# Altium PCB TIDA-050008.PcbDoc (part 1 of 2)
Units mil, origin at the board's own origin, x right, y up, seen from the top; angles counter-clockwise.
Board outline 3500 x 2500 mil, 4 copper layers (Top Layer, Signal Layer 1, Signal Layer 2, Bottom Layer), stack 38.4 mil thick; 136 components, 48 nets, 303 pads, 230 vias.
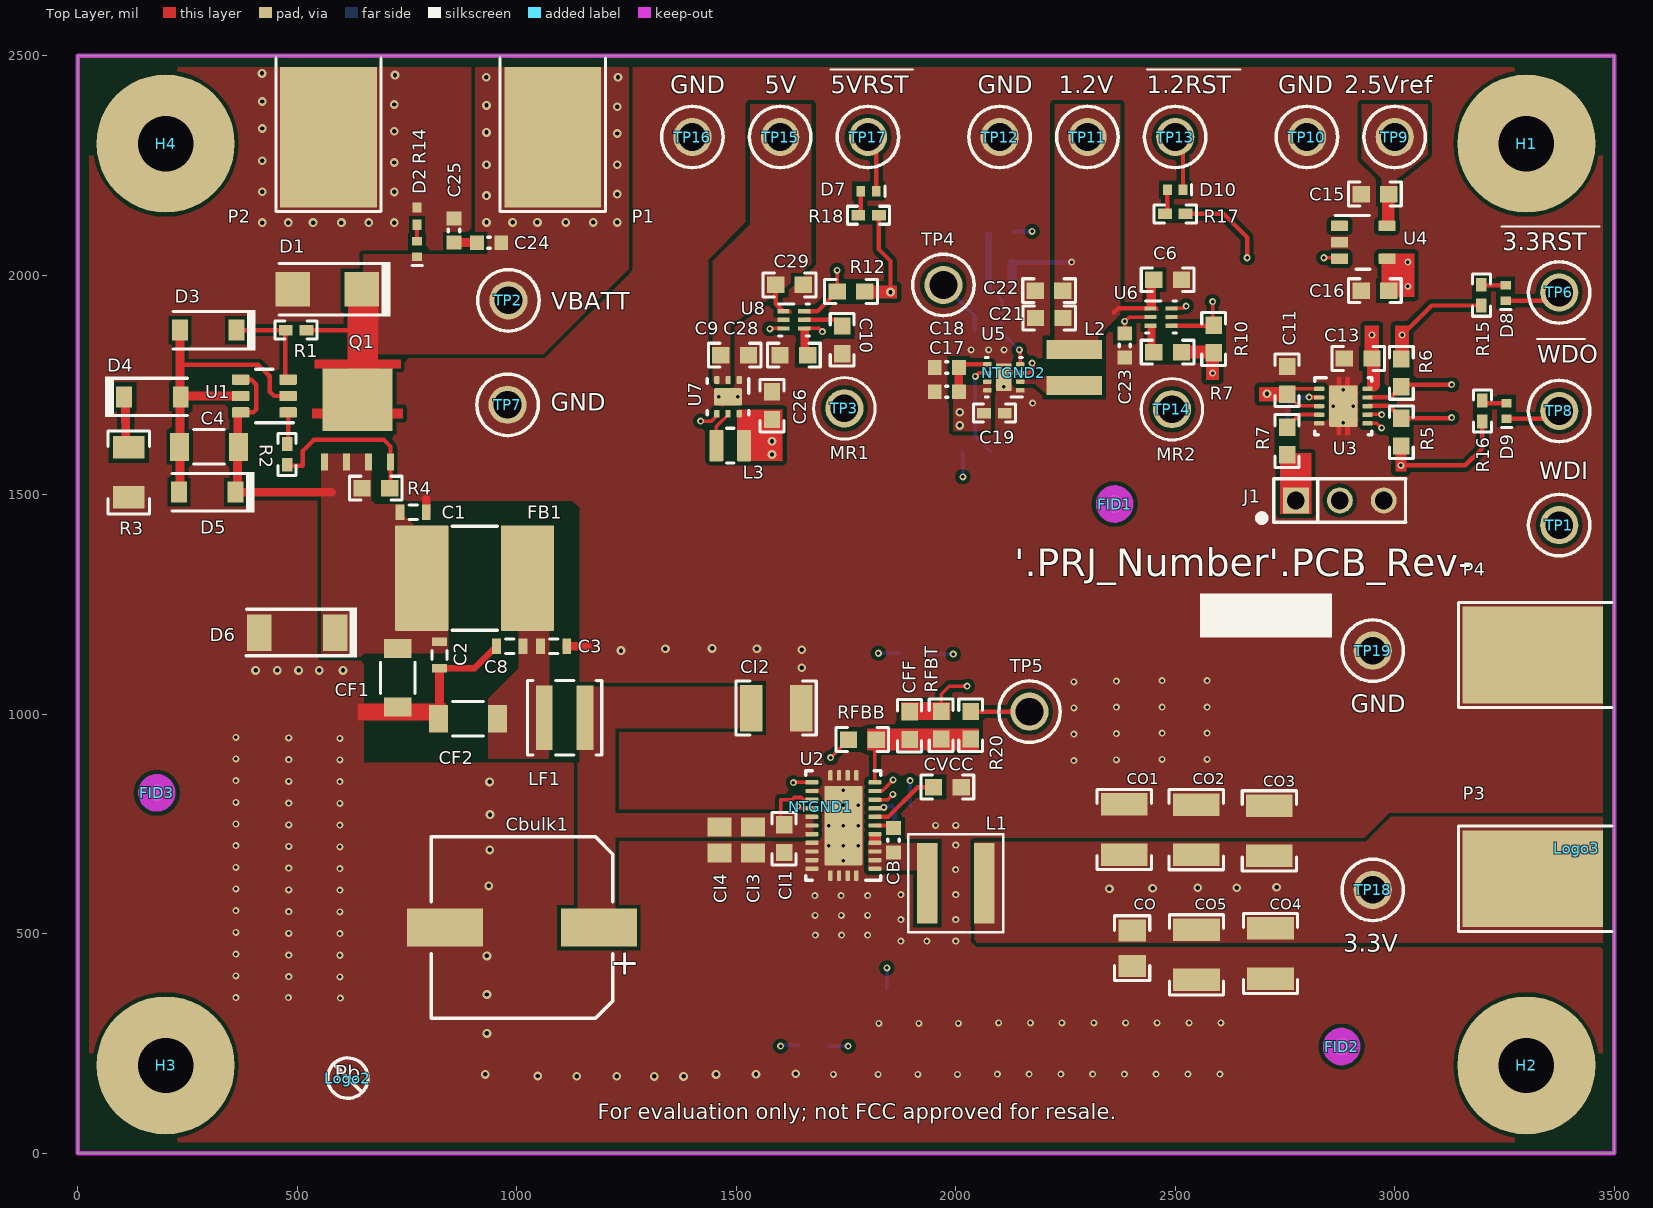
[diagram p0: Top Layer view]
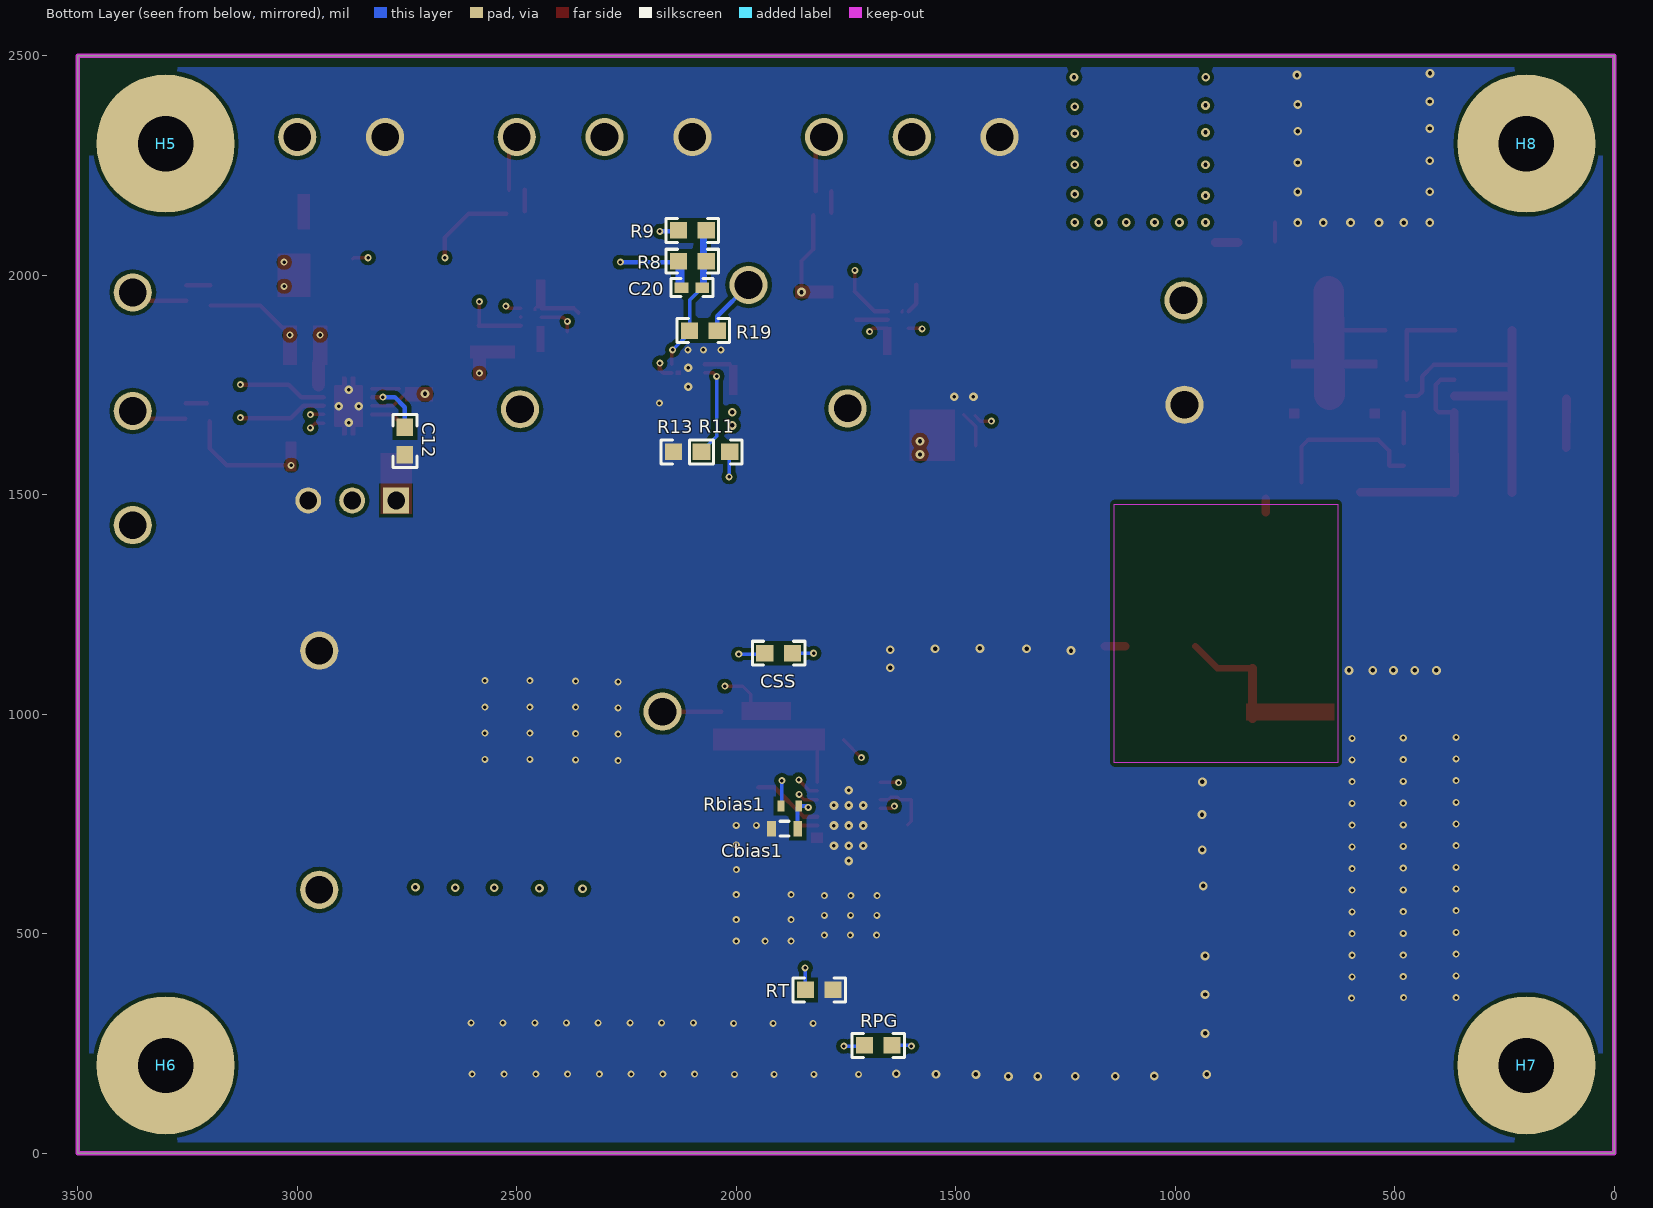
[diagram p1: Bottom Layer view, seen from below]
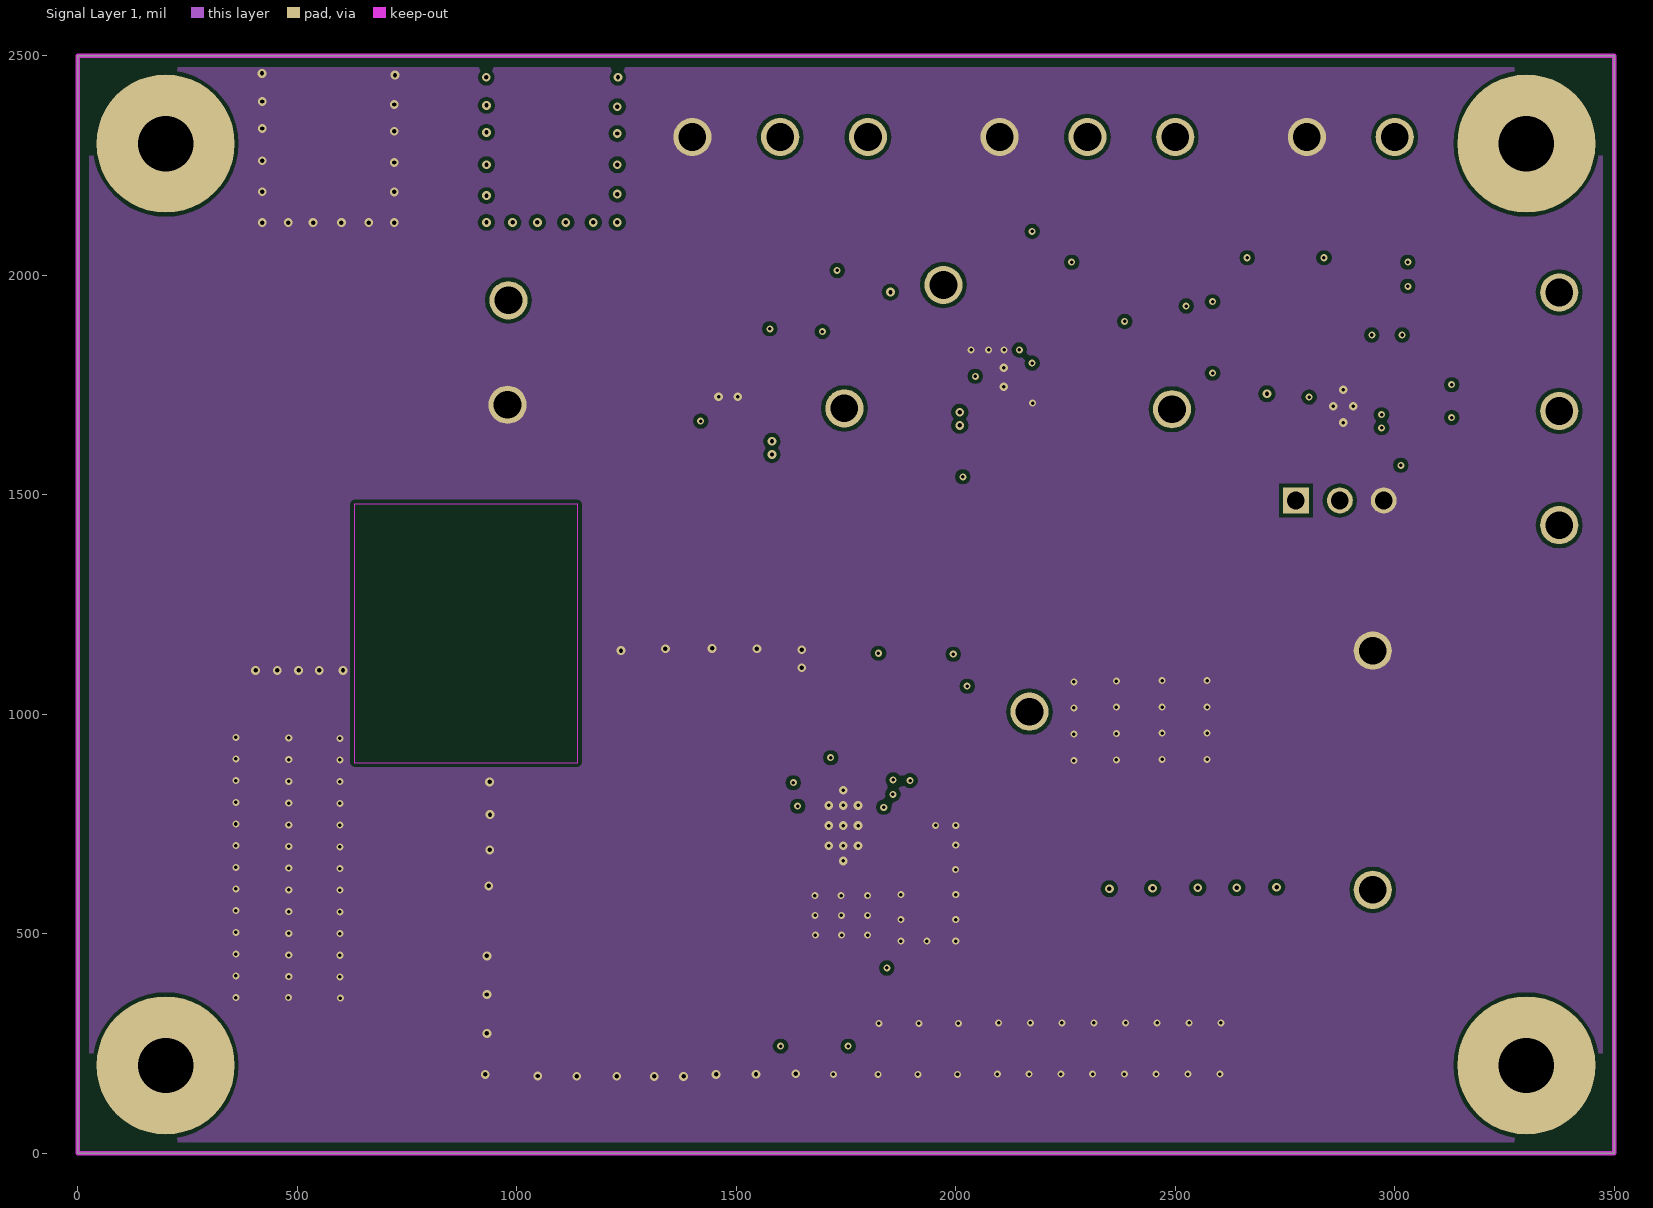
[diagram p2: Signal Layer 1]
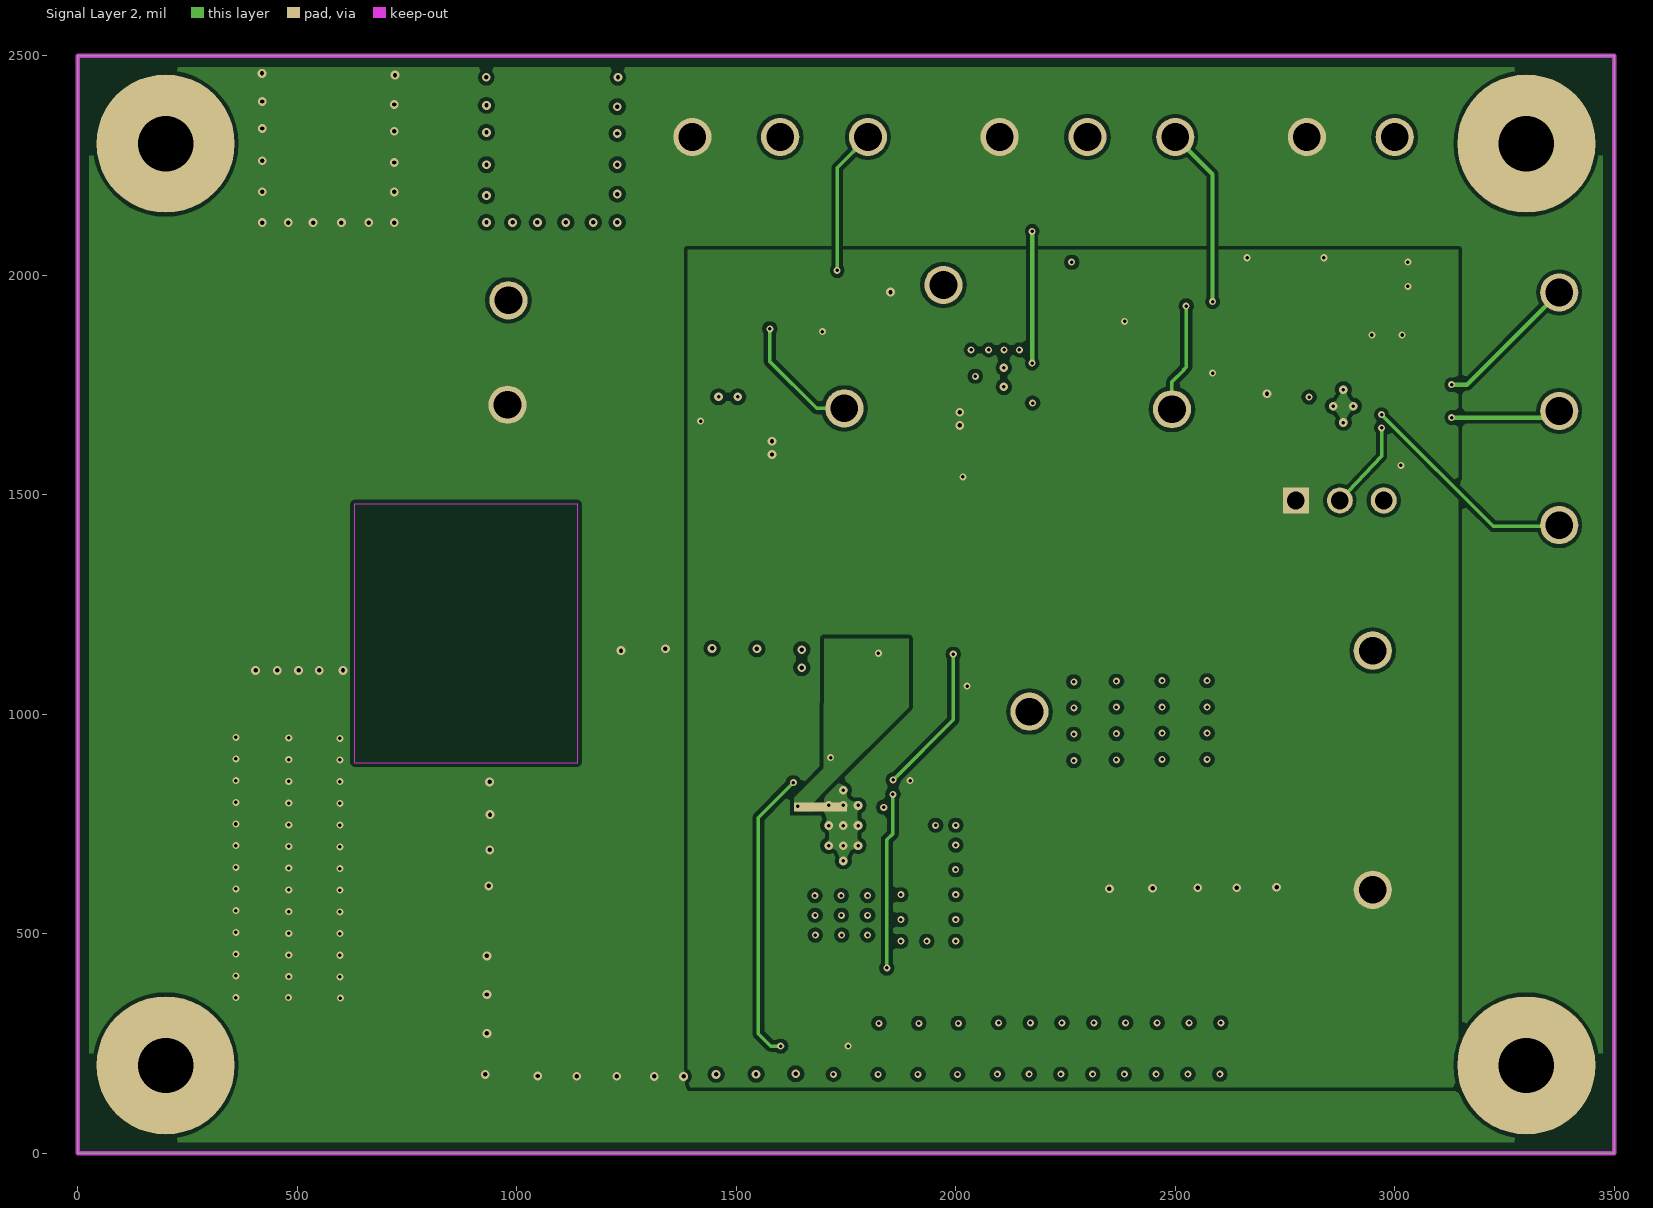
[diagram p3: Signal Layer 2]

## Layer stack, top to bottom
Top Solder: solder mask 0.4, Solder Resist, Dk 3.5
Top Layer: signal copper 2.8
Dielectric1: core 10, FR-4, Dk 4.2
Signal Layer 1: signal copper 1.4
Dielectric 2: core 10, FR-4, Dk 4.2
Signal Layer 2: signal copper 1.4
Dielectric3: core 10, FR-4, Dk 4.2
Bottom Layer: signal copper 2.8
Bottom Solder: solder mask 0.4, Solder Resist, Dk 3.5

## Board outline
0,0 3500,0 3500,2500 0,2500

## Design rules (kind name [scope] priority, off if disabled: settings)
AcuteAngle [All] p1: minimum=4.50000000000000E+0001 checktracksonly=FALSE
AssemblyTestPointUsage [All] p1: valid=2
BoardOutlineClearance BoardOutlineClearance_MountingHoles [OnCopper and InComponentClass('Mounting Holes')] p1: gap=40 ignorepadtopadclearanceinfootprint=FALSE
BoardOutlineClearance BoardOutlineClearance_Poly [OnCopper and IsPoly] p2: gap=25 ignorepadtopadclearanceinfootprint=FALSE
BoardOutlineClearance [OnCopper and Not InComponentClass('Logo') and not InComponentClass('FiducialMark') and not InRegion(1000,500,4000,800) and not InPoly] p3: gap=25 ignorepadtopadclearanceinfootprint=FALSE
Clearance Clearance_1 [(InNet('1.2RESET') AND InComponent('C1'))] p1: gap=10 ignorepadtopadclearanceinfootprint=FALSE except(0: Arc-Hole Track-Hole SMDPad-Hole THPad-Hole Via-Hole Fill-Hole Poly-Hole Region-Hole Text-Hole)
Clearance Clearance_Keepouts [((IsTrack Or IsArc) And Not InPoly) And IsFree and IsKeepOut vs ((IsTrack Or IsArc) And Not InPoly) And IsFree and IsKeepOut] p2: gap=0 ignorepadtopadclearanceinfootprint=FALSE
Clearance Clearance_Poly [InPolygon] p3: gap=9 ignorepadtopadclearanceinfootprint=FALSE except(0: Arc-Hole Track-Hole SMDPad-Hole THPad-Hole Via-Hole Fill-Hole Poly-Hole Region-Hole Text-Hole)
Clearance Clearance_FiducialMark [IsKeepOut and InComponentClass('FiducialMark') vs IsPad and InComponentClass('FiducialMark')] p4: gap=0 ignorepadtopadclearanceinfootprint=FALSE
Clearance [All] p5: gap=4 ignorepadtopadclearanceinfootprint=FALSE
ComponentClearance ComponentClearance_R11andR13 [InComponent('R11') vs InComponent('R13')] p1: gap=-1 collisioncheckmode=3 verticalgap=10 showdistances=FALSE
ComponentClearance ComponentClearance_NetTietoGND [(InComponent('NTGND1') OR InComponent('NTGND2')) vs (InComponent('U2') OR InComponent('U5'))] p2: gap=-1 collisioncheckmode=3 verticalgap=10 showdistances=FALSE
ComponentClearance ComponentClearance_MountingHoles_FiducialMarks [InComponentClass('Mounting Holes') vs InComponentClass('FiducialMark')] p3: gap=50 collisioncheckmode=3 verticalgap=10 showdistances=FALSE
ComponentClearance ComponentClearance_Shunt [InComponentClass('Header') vs InComponentClass('Shunt')] p4: gap=0 collisioncheckmode=3 verticalgap=0 showdistances=FALSE
ComponentClearance ComponentClearance_Logo [InComponentClass('Logo')] p5: gap=50 collisioncheckmode=3 verticalgap=10 showdistances=FALSE
ComponentClearance ComponentClearance_ScrewToNut [(HasFootprint('NY PMS 440 0025 PH')) vs (HasFootprint('Keystone_1902C'))] p6: gap=5 collisioncheckmode=3 verticalgap=10 showdistances=FALSE
ComponentClearance ComponentClearance_MountingHoles [InComponentClass('Mounting Holes')] p7: gap=100 collisioncheckmode=3 verticalgap=100000 showdistances=FALSE
ComponentClearance ComponentClearance_SmallPassives [HasFootprint('0201*') or HasFootprint('0402*') or HasFootprint('0508') or HasFootprint('0603*') or HasFootprint('0612') or HasFootprint('0805*') or HasFootprint('0815*') or HasFootprint('0830*') or HasFootprint('1206*') or HasFootprint('1210*') or HasFootprint('1808*') or HasFootprint('1812*') or HasFootprint('1825*') or HasFootprint('2010*') or HasFootprint('2220*') or HasFootprint('2225*') or HasFootprint('2512*') or HasFootprint('2728*') or HasFootprint('3518*') vs HasFootprint('0201*') or HasFootprint('0402*') or HasFootprint('0508') or HasFootprint('0603*') or HasFootprint('0612') or HasFootprint('0805*') or HasFootprint('0815*') or HasFootprint('0830*') or HasFootprint('1206*') or HasFootprint('1210*') or HasFootprint('1808*') or HasFootprint('1812*') or HasFootprint('1825*') or HasFootprint('2010*') or HasFootprint('2220*') or HasFootprint('2225*') or HasFootprint('2512*') or HasFootprint('2728*') or HasFootprint('3518*')] p8: gap=14.96 collisioncheckmode=3 verticalgap=10 showdistances=FALSE
ComponentClearance ComponentClearance_THtoSMT [IsThruComponent vs IsSMTComponent] p9: gap=40 collisioncheckmode=3 verticalgap=30 showdistances=FALSE
ComponentClearance ComponentClearance_THtoTH [IsThruComponent vs IsThruComponent] p10: gap=30 collisioncheckmode=3 verticalgap=30 showdistances=FALSE
ComponentClearance [All] p11: gap=15 collisioncheckmode=3 verticalgap=10 showdistances=FALSE
DiffPairsRouting [All] p1: maxlimit=100 minlimit=10 mostfreqgap=10 toplayer_minwidth=15 toplayer_maxwidth=15 toplayer_prefwidth=15 midlayer1_minwidth=15 midlayer1_maxwidth=15 midlayer1_prefwidth=15 midlayer2_minwidth=15 midlayer2_maxwidth=15 midlayer2_prefwidth=15 bottomlayer_minwidth=15 bottomlayer_maxwidth=15 bottomlayer_prefwidth=15 maxuncoupledlength=1000
FabricationTestPointUsage TestPointUsage [All] p1: valid=2 allowmultiple=FALSE
FabricationTestpoint Testpoint [All] p1: side=3 testpointundercomponent=TRUE minsize=40 maxsize=100 preferedsize=60 minholesize=0 maxholesize=40 preferedholesize=32 testpointgrid=1 allowsidetop=TRUE allowsidebottom=TRUE usegrid=TRUE gridtolerance=0.01
FanoutControl Fanout_LCC [IsLCC] p1: bgadir=Out bgaviamode=Centered fanoutstyle=Auto fanoutdirection=Alternating viagrid=1 // Fanout_LCC (Default Rule)
FanoutControl Fanout_BGA [IsBGA] p2: bgadir=Out bgaviamode=Centered fanoutstyle=Auto fanoutdirection=Alternating viagrid=1 // Fanout_BGA (Default Rule)
FanoutControl Fanout_Default [All] p4: bgadir=Out bgaviamode=Centered fanoutstyle=Auto fanoutdirection=Alternating viagrid=1 // Fanout_Default (Default Rule)
FanoutControl Fanout_Small [(CompPinCount < 5)] p5: bgadir=Out bgaviamode=Centered fanoutstyle=Auto fanoutdirection=OutThenIn viagrid=1 // Fanout_Small (Default Rule)
HoleSize [All] p1: absolutevalues=TRUE maxlimit=251 minlimit=7.87 maxpercent=80.000 minpercent=20.000
MinimumAnnularRing MinimumAnnularRing_ThermalPadVias [IsVia and InAnyComponent] p1: minimumring=5.8
MinimumAnnularRing [All] p2: minimumring=4
MinimumSolderMaskSliver MinimumSolderMaskSliver_Logo [InComponentClass('Logo') vs InComponentClass('Logo')] p1: minsoldermaskwidth=0.7
MinimumSolderMaskSliver [All] p2: minsoldermaskwidth=2.4
PlaneConnect [All] p1: planeconnectstyle=Direct reliefexpansion=10 reliefentries=4 reliefconductorwidth=10 reliefairgap=10
PolygonConnect [All] p1: connectstyle=Direct reliefconductorwidth=10 reliefentries=4 polygonreliefangle="90 Angle" airgapwidth=10
RoutingVias ThermalPadVias [IsVia and InAnyComponent] p1: holewidth=7.87 width=19.68 viastyle="Through Hole" minholewidth=7.87 minwidth=19.68 maxholewidth=12.99 maxwidth=23.62
RoutingVias [All] p2: holewidth=16 width=34 viastyle="Through Hole" minholewidth=8 minwidth=16 maxholewidth=40 maxwidth=65
SilkToBoardRegionClearance [Not ((IsComment or IsDesignator) And (Hide <> 'False')) and not InRegion(1000,500,4000,800)] p1:
SilkToSilkClearance SilkToSilkClearance_Pb-FreeLogo [(HasFootprint('Pb-Free_Overlay_Medium') OR HasFootprint('Pb-Free_Overlay_Small')) vs (HasFootprint('Pb-Free_Overlay_Medium') OR HasFootprint('Pb-Free_Overlay_Small'))] p1: silktosilkclearance=0
SilkToSilkClearance [All] p2: silktosilkclearance=2
SilkToSolderMaskClearance SilkToComponentPadClearance [(IsPad or IsFill or IsRegion) and InAnycomponent] p1: minsilkscreentomaskgap=3 clearancetoexposedcopper=TRUE
SilkToSolderMaskClearance "Silk to Solder Mask Opening" [All] p2: minsilkscreentomaskgap=0.5 clearancetoexposedcopper=FALSE
SolderMaskExpansion [All] p1: expansion=1.97
Width [All] p1: maxlimit=100 minlimit=6 preferedwidth=10 checkconnectedcopper=TRUE
15 further rules are at their usual default settings.

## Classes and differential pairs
component class "Mounting Holes": H1 H2 H3 H4
component class TIDA-050008_EVM_Hardware: FID1 FID2 FID3 H1 H2 H3 H4 H5 H6 H7 H8 Logo2 Logo3 ZZ1 ZZ2 ZZ3 ZZ4
component class FiducialMark: FID1 FID2 FID3
component class AssemblyNote: ZZ1 ZZ2 ZZ3 ZZ4
component class Header: J1
component class "TIDA-050008_Main Supply": C1 C2 C3 C4 C8 C24 C25 CB Cbias1 Cbulk1 CF1 CF2 CFF CI1 CI2 CI3 CI4 CO CO1 CO2 CO3 CO4 CO5 CSS CVCC D1 D2 D3 D4 D5 D6 FB1 L1 LF1 NTGND1 P1 P2 P3 P4 Q1 R1 R2 R3 R4 R14 R20 Rbias1 RFBB RFBT RPG RT TP2 TP5 TP7 TP18 TP19 U1 U2
component class "TIDA-050008_CAN Supply and Supervisor": C9 C10 C26 C28 C29 D7 L3 R12 R18 TP3 TP15 TP16 TP17 U7 U8
component class "TIDA-050008_Watchdog and Vref": C11 C12 C13 C15 C16 D8 D9 J1 R5 R6 R7 R15 R16 TP1 TP6 TP8 TP9 TP10 U3 U4
component class "TIDA-050008 Core Supply and Supervisor": C6 C17 C18 C19 C20 C21 C22 C23 D10 L2 NTGND2 R7 R8 R9 R10 R11 R13 R17 R19 TP4 TP11 TP12 TP13 TP14 U5 U6

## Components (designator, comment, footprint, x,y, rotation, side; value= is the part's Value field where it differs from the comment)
C1 "GCM188R71C104KA37J" 0603S 764.01,1460 r0 top value=0.1uF
C2 "GCM188R71C104KA37J" 0603S 824.01,1135 r270 top value=0.1uF
C3 "GCM188R71C104KA37J" 0603S 1084.01,1155 r0 top value=0.1uF
C4 "C3216X7R1V106M160AC" 1206_190 299,1609 r180 top value=10uF
C6 "GRM188R71C103KA01D" 0603 2482.6,1989.85 r0 top value=0.01uF
C8 "GCM188R71C104KA37J" 0603S 984.01,1155 r180 top value=0.1uF
C9 "GRM188Z71A106MA73D" 0603 1496.34,1818.07 r180 top value=10uF
C10 "GRM188R71E184KA88D" 0603 1741.34,1853.07 r270 top value=0.18uF
C11 "GRM188R71C104KA01D" 0603 2755,1760.65 r90 top value=0.1uF
C12 "DNP" 0603 2755,1622.6 r270 bottom value=0.1uF
C13 "GRM188R71C103KA01D" 0603 2916.73,1810.52 r180 top value=0.01uF
C15 "GRM188Z71C225KE43" 0603 2955,2185 r180 top value=2.2uF
C16 "GCM188R71C105KA64D" 0603 2955,1965 r180 top value=1uF
C17 "GRM188Z71A106MA73D" 0603L 1979.55,1734.91 r180 top value=10uF
C18 "GRM188Z71A106MA73D" 0603L 1979.55,1789.91 r180 top value=10uF
C19 "GCM155R71H471KA37D" 0402 2088,1686 r0 top value=470pF
C20 "C1005C0G1H680J050BA" 0402 2101,1972 r180 bottom value=68pF
C21 "GRM188Z71A106MA73D" 0603 2213,1902.8 r180 top value=10uF
C22 "DNP" 0603 2212.57,1965 r180 top value=22uF
C23 "GRM188R71C104KA01D" 0603L 2385,1840 r270 top value=0.1uF
C24 "CGA3E3X7R1H224K080AB" 0603L 937,2074 r0 top value=0.22uF
C25 "CGA3E3X7R1H224K080AB" 0603L 857,2102 r90 top value=0.22uF
C26 "GRM188Z71C225KE43" 0603 1581.34,1703.07 r90 top value=2.2uF
C28 "GRM188R71C104KA01D" 0603 1631.34,1818.07 r180 top value=0.1uF
C29 "GRM188R71C103KA01D" 0603 1621.34,1978.07 r0 top value=0.01uF
CB "GRM188R61E474KA12D" 0603L 1858,713 r270 top value=0.47uF
Cbias1 "GCM188R71C104KA37J" 0603S 1889.99,739.5 r0 bottom value=0.1uF
Cbulk1 "HHXB500ARA101MJA0G" HXB_JA0 1011.99,514 r180 top value=100uF
CF1 "C3216X7R1H475K160AC" 1206_180 729,1083 r270 top value=4.7uF
CF2 "C3216X7R1H475K160AC" 1206_180 889.01,990 r180 top value=4.7uF
CFF "06035A4R7CAT2A" 0603 1895,974 r270 top value=4.7pF
CI1 "GRM21BR71H474KA88L" 0603 1608.99,716.5 r90 top value=0.47uF
CI2 "GRM32ER71H106KA12L" 1210_270 1591,1014 r180 top value=10uF
CI3 "C2012X5R1H225K125AB" 0805L 1538,714 r270 top value=2.2uF
CI4 "C2012X5R1H225K125AB" 0805L 1462,714 r270 top value=2.2uF
CO "GRM21BR71H474KA88L" 0805_HV 2401.99,467 r90 top value=0.47uF
CO1 "GRM32ER71C226KE18L" 1210_270 2383.99,737.5 r90 top value=22uF
CO2 "GRM32ER71C226KE18L" 1210_270 2547.99,737 r90 top value=22uF
CO3 "GRM32ER71C226KE18L" 1210_270 2714.49,734.5 r90 top value=22uF
CO4 "GRM32ER71C226KE18L" 1210_270 2716.99,455 r270 top value=22uF
CO5 "GRM32ER71C226KE18L" 1210_270 2548.49,452 r270 top value=22uF
CSS "06031C103MAT2A" 0603 1903.49,1139 r180 bottom value=0.01uF
CVCC "GRM188C81A225KE34D" 0603 1981,834 r0 top value=2.2uF
D1 "SMAJ28CA" SMA 568,1968 r180 top value=28V
D2 "SML-P12UTT86" SML-P1_RED 772.8,2059.87 r90 top value=Red
D3 "BAT46W-E3-08" SOD-123 297.25,1875 r180 top value=100V
D4 "BAT46W-E3-08" SOD-123 170,1723 r0 top value=100V
D5 "BZT52C15-7-F" SOD-123 295,1506 r180 top value=15V
D6 "DB2430100L" SOD-128 500,1186 r180 top value=30V
D7 "SML-P12UTT86" SML-P1_RED 1801.34,2191.77 r180 top value=Red
D8 "SML-P12UTT86" SML-P1_RED 3252.59,1959.77 r90 top value=Red
D9 "SML-P12UTT86" SML-P1_RED 3254.77,1690.9 r90 top value=Red
D10 "SML-P12UTT86" SML-P1_RED 2500,2195 r180 top value=Red
FB1 "HR2220V801R-10" 2220_390 904.01,1310 r0 top value="800 ohm"
FID1 "Fiducial" Fiducial10-20 2362,1479 r0 top
FID2 "Fiducial" Fiducial10-20 2879,243 r0 top
FID3 "Fiducial" Fiducial10-20 180,821 r0 top
H1 "NY PMS 440 0025 PH" "NY PMS 440 0025 PH" 3300,2300 r0 top locked
H2 "NY PMS 440 0025 PH" "NY PMS 440 0025 PH" 3300.01,200 r0 top locked
H3 "NY PMS 440 0025 PH" "NY PMS 440 0025 PH" 200,200 r0 top locked
H4 "NY PMS 440 0025 PH" "NY PMS 440 0025 PH" 200,2300 r0 top locked
H5 "1902C" Keystone_1902C 3300,2300 r180 bottom locked
H6 "1902C" Keystone_1902C 3300.01,200 r180 bottom locked
H7 "1902C" Keystone_1902C 200,200 r180 bottom locked
H8 "1902C" Keystone_1902C 200,2300 r180 bottom locked
J1 "PEC03SAAN" CONN_PEC03SAAN 2875,1487 r0 top
L1 "XAL5030-222MEB" XAL5030 2000,615 r0 top value=2.2uH
L2 "XFL3010-102MEB" XFL3010 2270,1790 r90 top value=1uH
L3 "LQM2MPN2R2NG0" LQM2MPN_G0 1486.34,1611.77 r180 top value=2.2uH
LF1 "XAL4020-601MEB" XAL4020 1109,992 r0 top value=600nH
Logo2 "Pb-Free Symbol" Pb-Free_Overlay_Small 615,171 r0 top
Logo3 "FCC disclaimer" FCC_disclaimer 3415.01,695 r0 top
NTGND1 "Net-Tie" Net-Tie_20milWide_60milLong 1692,789 r180 top net-tie
NTGND2 "Net-Tie" Net-Tie_10mil 2132,1778 r0 top net-tie
P1 "VBATT" 6091 1082,2500 r270 top
P2 "GND" 6092 571,2500 r270 top
P3 "3.3Vout" 6091 3500,625 r180 top
P4 "GND" 6092 3500,1135 r180 top
Q1 "SQJ465EP" PowerPAK_SO-8L 637.25,1685 r90 top value=-60V
R1 "ERJ-2GEJ103X" 0402 497.25,1875 r0 top value=10k
R2 "CRCW040247R0JNED" 0402 477,1592 r270 top value=47
R3 "RC1206FR-07560RL" 1206 116,1551 r90 top value=560
R4 "RC0603JR-0756KL" 0603 679,1515 r0 top value=56k
R5 "CRCW0603100KFKEA" 0603 3015,1642.6 r270 top value=100k
R6 "CRCW0603100KFKEA" 0603 3015,1777.6 r90 top value=100k
R7 "DNP" 0603 2755,1622.6 r270 top value=10.0k
R7 "CRCW060310K0FKEA" 0603 2482.6,1824.85 r0 top value=10.0k
R8 "CRCW0603100KFKEA" 0603 2100,2032.2 r0 bottom value=100k
R9 "CRCW0603100KFKEA" 0603 2100,2102.2 r180 bottom value=100k
R10 "CRCW0603100KFKEA" 0603 2587.6,1854.85 r270 top value=100k
R11 "CRCW06030000Z0EA" 0603 2046.5,1597.62 r180 bottom value=0
R12 "CRCW0603100KFKEA" 0603 1761.34,1963.07 r0 top value=100k
R13 "DNP" 0603 2111.5,1597.62 r180 bottom value=0
R14 "CRCW04022K20FKED" 0402L 772.8,2134.87 r270 top value=2.20k
R15 "CRCW04021K00FKED" 0402 3197.59,1954.77 r90 top value=1.00k
R16 "CRCW04021K00FKED" 0402 3199.77,1690.9 r90 top value=1.00k
R17 "CRCW04021K00FKED" 0402 2500,2140 r180 top value=1.00k
R18 "CRCW04021K00FKED" 0402 1801.34,2136.77 r180 top value=1.00k
R19 "CRCW0603825KFKEA" 0603 2075,1874 r0 bottom value=825k
R20 "CRCW0603562KFKEA" 0603 2034,975 r270 top value=562k
Rbias1 "CRCW04023R00JNED" 0402S 1877.99,791 r0 bottom value=3.0
RFBB "CRCW060343K2FKEA" 0603 1787.18,942.2 r0 top value=43.2k
RFBT "CRCW0603100KFKEA" 0603 1967,975 r90 top value=100k
RPG "CRCW0603100KFKEA" 0603 1676.49,245.5 r0 bottom value=100k
RT "CRCW060317K4FKEA" 0603 1811,372 r180 bottom value=17.4k
TP1 "WDI" Keystone5127 3374.77,1430.9 r0 top
TP2 "VBATT" Keystone5010 981,1943 r0 top
TP3 "MR1" Keystone5126 1746.34,1696.77 r0 top
TP4 "V_CTRL2" Keystone5012 1972,1978 r0 top
TP5 "V_CTRL1" Keystone5012 2168,1006 r0 top
TP6 "3.3RST" Keystone5014 3374.77,1960.9 r0 top
TP7 "GND" Keystone5011 979,1705 r0 top
TP8 "WDO" Keystone5013 3374.77,1690.9 r0 top
TP9 "2.5Vref" Keystone5010 3000,2315 r0 top
TP10 "GND" Keystone5011 2800,2315 r0 top
TP11 "1.2V" Keystone5010 2300,2315 r0 top
TP12 "GND" Keystone5011 2100,2315 r0 top
TP13 "1.2RST" Keystone5014 2500,2315 r0 top
TP14 "MR2" Keystone5126 2492.6,1694.85 r0 top
TP15 "5V" Keystone5010 1600,2315 r0 top
TP16 "GND" Keystone5011 1400,2315 r0 top
TP17 "5VRST" Keystone5014 1800,2315 r0 top
TP18 "3.3V" Keystone5010 2950.01,600 r0 top
TP19 "GND" Keystone5011 2950.01,1145 r0 top
U1 "TLV1805QDBVRQ1" DBV0006A_N 425,1725 r180 top
U2 "LM73605QRNPRQ1" RNP0030A 1743.99,746.5 r180 top
U3 "TPS3850H33QDRCRQ1" DRC0010R 2883,1702 r0 top
U4 "LM4132AQ1MFT2.5" DBV0005A_N 2928.53,2075.2 r0 top
U5 "TPS62065QDSGRQ1" DSG0008A 2109.55,1767.62 r180 top
U6 "TPS3703A4120DSERQ1" DSE0006A 2467.6,1904.85 r0 top
U7 "TPS61240TDRVRQ1" DRV0006A 1481.34,1723.07 r270 top
U8 "TPS389050GQDSERQ1" DSE0006A 1631.34,1898.58 r0 top
ZZ1 "This Assembly Note is for PCB labels only" AssemblyNoteLabel -120,4120 r0 top
ZZ2 "This Assembly Note will show in the PcbDoc and associated outputs" AssemblyNote -115,4019.12 r0 top
ZZ3 "This Assembly Note will show in the PcbDoc and associated outputs" AssemblyNote -120,3930 r0 top
ZZ4 "This Assembly Note will show in the PcbDoc and associated outputs" AssemblyNote -120,3860 r0 top

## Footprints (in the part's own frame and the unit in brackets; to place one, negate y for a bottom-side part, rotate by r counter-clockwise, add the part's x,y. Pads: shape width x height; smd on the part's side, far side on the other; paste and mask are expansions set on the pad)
0402 [mm] "0402 from SM-752 data"
  rect 0.8x0.6 smd: 1(-0.6,0) 2(0.6,0)
  silkscreen extent -1.22,-0.52 1.22,0.52, body extent -0.55,-0.3 0.55,0.3, height 0.6
0402L [mm] "0402 from SM-752 data"
  rect 0.6x0.5 smd: 1(-0.5,0) 2(0.5,0)
  body extent -0.55,-0.3 0.55,0.3, height 0.6
0402S [mil] "Based on C0402S footprint from PADS legacy"
  rect 15x24 smd: 1(-20,0) 2(20,0)
  body extent -22,-12 22,12, height 24
0603 [mm] "0603 from SM-752 data"
  rect 1x0.95 smd: 1(-0.8,0) 2(0.8,0)
  silkscreen extent -1.52,-0.69 1.52,0.69, body extent -0.87,-0.47 0.87,0.47, height 1
0603L [mm] "0603 from SM-752 data"
  rect 0.8x0.85 smd: 1(-0.7,0) 2(0.7,0)
  silkscreen extent -0.07,-0.33 0.07,0.33, body extent -0.87,-0.47 0.87,0.47, height 1
0603S [mil]
  rect 20x35 smd: 1(-30,0) 2(30,0)
  silkscreen extent -10,-17 10,17, body extent -34,-19 34,19, height 39
0805_HV [mil] "0805 with 30mil clearance between pads"
  rect 50x63 smd: 1(-40,0) 2(40,0)
  silkscreen extent -74,-40 74,40, body extent -43,-29 43,29, height 57
0805L [mm] "0805 from SM-752 data"
  rect 1.1x1.4 smd: 1(-0.75,0) 2(0.75,0)
  body extent -1.1,-0.72 1.1,0.72, height 1.45
1206 [mm] "1206 from SM-752 data"
  rect 1.3x1.85 smd: 1(-1.45,0) 2(1.45,0)
  silkscreen extent -2.4,-1.21 2.4,1.21, body extent -1.7,-0.9 1.7,0.9, height 1.35
1206_180 [mm] "1206_180"
  rect 1.1x1.6 smd: 1(-1.7,0) 2(1.7,0)
  silkscreen extent -0.9,-1 0.9,1, body extent -1.75,-0.95 1.75,0.95, height 1.8
1206_190 [mm] "1206_190"
  rect 1.1x1.6 smd: 1(-1.7,0) 2(1.7,0)
  silkscreen extent -0.9,-1 0.9,1, body extent -1.75,-0.95 1.75,0.95, height 1.9
1210_270 [mm] "1210"
  rect 1.3x2.7 smd: 1(-1.45,0) 2(1.45,0)
  silkscreen extent -2.32,-1.57 2.32,1.57, body extent -1.7,-1.35 1.7,1.35, height 2.7
2220_390 [mm] "Laird recommended land pattern"
  rrect3% 3.07x6.1 smd: 1(-3.06,0) 2(3.06,0)
  silkscreen extent -1.3,-3 1.3,3, body extent -2.8,-2.54 2.79,2.54, height 3.9
6091 [mil] "Keystone Insulated End Launch Banana Jack"
  rect 320x220 smd: 1(185,0)
  silkscreen extent 5,-120 355,120, body extent -666,-216 271,216, height 227
6092 [mil] "Keystone Insulated End Launch Banana Jack"
  rect 320x220 smd: 1(185,0)
  silkscreen extent 5,-120 355,120, body extent -666,-216 271,216, height 227
AssemblyNote [mil] "Assembly Note"
AssemblyNoteLabel [mil] "Assembly Note for PCB Labels"
CONN_PEC03SAAN [mm] "SULLINS"
  rect 1.5x1.5 hole 1.016: 1(-2.54,0)
  round 1.5 hole 1.016: 2(0,0) 3(2.54,0)
  silkscreen extent -4.72,-1.27 3.81,1.27, body extent -3.84,-1.3 3.84,1.3, height 8.38
DBV0005A_N [mm] "SOT23, 5-Leads, Body 2.9x1.6mm, Pitch 0.95mm, Lead Span 2.8mm, IPC Medium Density"
  rrect17% 1x0.6 smd: 1(-1.375,0.95) 2(-1.375,0) 3(-1.375,-0.95) 4(1.375,-0.95) 5(1.375,0.95)
  silkscreen extent -1.63,-1.55 0.38,1.55, body extent -1.42,-1.46 1.42,1.46, height 1.09
DBV0006A_N [mm] "SOT23, 6-Leads, Body 2.9x1.6mm, Pitch 0.95mm, Lead Span 2.8mm, IPC Medium Density"
  rrect17% 1x0.6 smd: 1(-1.375,0.95) 2(-1.375,0) 3(-1.375,-0.95) 4(1.375,-0.95) 5(1.375,0) 6(1.375,0.95)
  silkscreen extent -1.68,-1.55 0.5,1.55, body extent -1.42,-1.46 1.42,1.46, height 1.12
DRC0010R [mm] "VSON-10"
  rrect40% 0.6x0.25 smd: 1(-1.4,1) 2(-1.4,0.5) 3(-1.4,0) 4(-1.4,-0.5) 5(-1.4,-1) 6(1.4,-1) 7(1.4,-0.5) 8(1.4,0) 9(1.4,0.5) 10(1.4,1)
  rrect12% 1.65x2.4 smd paste-1 mask-2: 11(0,0)
  Top Layer region: -0.375,-1.65 -0.375,-1.2 -0.775,-1.2 -0.794,-1.196 -0.81,-1.185 -0.821,-1.169 -0.825,-1.15 -0.825,-1.15 -0.825,1.15 -0.821,1.169 -0.81,1.185 -0.794,1.196 -0.775,1.2 -0.775,1.2 -0.375,1.2 -0.375,1.65 -0.371,1.669 -0.36,1.685 -0.344,1.696 -0.325,1.7 -0.325,1.7 -0.325,1.7 -0.175,1.7 -0.175,1.7 -0.156,1.696 -0.14,1.685 -0.129,1.669 -0.125,1.65 -0.125,1.65 -0.125,1.2 0.125,1.2 0.125,1.65 0.129,1.669 0.14,1.685 0.156,1.696 0.175,1.7 0.175,1.7 0.175,1.7 0.325,1.7 0.325,1.7 0.344,1.696 0.36,1.685 0.371,1.669 0.375,1.65 0.375,1.65 0.375,1.2 0.775,1.2 0.794,1.196 0.81,1.185 0.821,1.169 0.825,1.15 0.825,1.15 0.825,-1.15 0.821,-1.169 0.81,-1.185 0.794,-1.196 0.775,-1.2 0.775,-1.2 0.375,-1.2 0.375,-1.65 0.371,-1.669 0.36,-1.685 0.344,-1.696 0.325,-1.7 0.325,-1.7 0.175,-1.7 0.156,-1.696 0.14,-1.685 0.129,-1.669 0.125,-1.65 0.125,-1.65 0.125,-1.2 -0.125,-1.2 -0.125,-1.65 -0.129,-1.669 -0.14,-1.685 -0.156,-1.696 -0.175,-1.7 -0.175,-1.7 -0.325,-1.7 -0.344,-1.696 -0.36,-1.685 -0.371,-1.669 -0.375,-1.65
  silkscreen extent -1.65,-1.65 1.65,1.65, body extent -1.5,-1.5 1.5,1.5, height 0.87
DRV0006A [mm] "SON, 6-Leads, Body 2x2mm, Pitch 0.65mm, Thermal Pad 1.6x1mm, TI Recommended"
  rrect33% 0.45x0.3 smd: 1(-0.975,0.65) 2(-0.975,0) 3(-0.975,-0.65) 4(0.975,-0.65) 5(0.975,0) 6(0.975,0.65)
  rrect14% 1x0.7 on Top Paste: 7(0,0.45) 7(0,-0.45)
  rrect10% 1x1.6 smd paste-0.5: 7(0,0)
  silkscreen extent -1.05,-1.2 1.05,1.2, body extent -1.05,-1.05 1.05,1.05, height 0.81
DSE0006A [mm] "TI recommended land pattern"
  rect 0.66x0.25 smd: 1(-0.62,0.5)
  rect 0.7x0.25 smd: 2(-0.6,0) 3(-0.6,-0.5) 4(0.6,-0.5) 5(0.6,0) 6(0.6,0.5)
  Top Layer region: -0.3,0.625 -0.25,0.625 -0.15,0.525 -0.15,0.375 -0.3,0.375
  silkscreen extent -0.9,-0.92 0.9,0.92, body extent -0.77,-0.77 0.77,0.77, height 0.8
DSG0008A [mm] "SON, 8-Leads, Body 2x2mm, Pitch 0.5mm, Thermal Pad 1.6x0.9mm, TI Recommended"
  rrect40% 0.5x0.25 smd: 1(-0.95,0.75) 2(-0.95,0.25) 3(-0.95,-0.25) 4(-0.95,-0.75) 5(0.95,-0.75) 6(0.95,-0.25) 7(0.95,0.25) 8(0.95,0.75)
  rrect14% 0.9x0.7 on Top Paste: 9(0,0.45) 9(0,-0.45)
  rrect11% 0.9x1.6 smd paste-0.45: 9(0,0)
  silkscreen extent -1.07,-1.15 1.07,1.15, body extent -1,-1 1,1, height 0.77
FCC_disclaimer [mil]
Fiducial10-20 [mm]
  round 1 smd mask+0.5: 1(0,0)
  Top Layer keep-out circle w1.178: c0,0 r0.5
HXB_JA0 [mm] "SMD, 2-Leads, Dia 10mm"
  rect 4.4x2.2 smd: 1(-4.45,0) 2(4.45,0)
  silkscreen extent -5.25,-5.25 5.25,5.25, body extent -5.25,-5.25 5.25,5.25, height 10.31
Keystone5010 [mil] "Keystone Multipurpose loops"
  round 87 hole 63: 1(0,0)
  silkscreen extent -70,-70 70,70, body extent -63,-63 63,62, height 319
Keystone5011 [mil] "Keystone Multipurpose loops"
  round 87 hole 63: 1(0,0)
  silkscreen extent -70,-70 70,70, body extent -63,-63 63,62, height 319
Keystone5012 [mil] "Keystone Multipurpose loops"
  round 87 hole 63: 1(0,0)
  silkscreen extent -70,-70 70,70, body extent -63,-63 63,62, height 319
Keystone5013 [mil] "Keystone Multipurpose loops"
  round 87 hole 63: 1(0,0)
  silkscreen extent -70,-70 70,70, body extent -63,-63 63,62, height 319
Keystone5014 [mil] "Keystone Multipurpose loops"
  round 87 hole 63: 1(0,0)
  silkscreen extent -70,-70 70,70, body extent -63,-63 63,62, height 319
Keystone5126 [mil] "Keystone Multipurpose loops"
  round 87 hole 63: 1(0,0)
  silkscreen extent -70,-70 70,70, body extent -63,-63 63,62, height 319
Keystone5127 [mil] "Keystone Multipurpose loops"
  round 87 hole 63: 1(0,0)
  silkscreen extent -70,-70 70,70, body extent -63,-63 63,62, height 319
Keystone_1902C [mil] "Hex Standoff, 4-40 threaded, nylon"
  body extent -145,-126 146,126, height 501
LQM2MPN_G0 [mm] "MuRata"
  rrect12% 0.8x1.8 smd: 1(-0.8,0) 2(0.8,0)
  silkscreen extent -0.2,-1 0.2,1, body extent -1.07,-0.87 1.07,0.87, height 1
Net-Tie_10mil [mil] "10mil net tie, no solder mask opening, no solder paste"
  rect 10x10 smd paste-5 mask-5: 1(-10,0) 2(10,0)
  Top Layer region: -6,5 6,5 6,-5 -6,-5
Net-Tie_20milWide_60milLong [mil] "20mil net tie, no solder mask opening, no solder paste"
  rect 60x20 on Mid2 paste-10 mask-10: 1(-30,0) 2(30,0)
"NY PMS 440 0025 PH" [mm] "4-40 nylon screw and mounting hole"
  round 8 hole 3.2: 1(0,0)
  body extent -3.3,-3.3 3.3,3.3, height 2.69
Pb-Free_Overlay_Small [mil]
  silkscreen extent -46,-46 46,46
PowerPAK_SO-8L [mm] "based on Vishay recommended land pattern Document 63818 Feb 7, 2012"
  rect 1x0.41 smd: 1(-2.805,1.905) 2(-2.805,0.635) 3(-2.805,-0.635) 4(-2.805,-1.905)
  rect 3.63x4.061 smd: 5(0.805,0)
  Top Layer region: 2.615,-2.5 3.125,-2.5 3.125,2.5 2.615,2.5
  Top Layer region: -0.298,2.03 0.297,2.03 0.297,2.64 -0.298,2.64
  Top Layer region: -0.297,-2.64 0.298,-2.64 0.298,-2.03 -0.297,-2.03
  body extent -3.07,-2.57 3.08,2.57, height 1.21
RNP0030A [mm] "QFN, 30-Leads, Body 6x4mm, Pitch 0.5mm, Thermal Pad 4.6x2.2mm"
  rrect40% 0.75x0.25 smd: 1(-1.825,2.5) 2(-1.825,2) 3(-1.825,1.5) 4(-1.825,1) 5(-1.825,0.5) 6(-1.825,0) 7(-1.825,-0.5) 8(-1.825,-1) 9(-1.825,-1.5) 10(-1.825,-2) 11(-1.825,-2.5) 16(1.825,-2.5) 17(1.825,-2) 18(1.825,-1.5) 19(1.825,-1) 20(1.825,-0.5) 21(1.825,0) 22(1.825,0.5) 23(1.825,1) 24(1.825,1.5) 25(1.825,2) 26(1.825,2.5)
  rrect40% 0.25x0.6 smd: 12(-0.75,-2.9) 13(-0.25,-2.9) 14(0.25,-2.9) 15(0.75,-2.9) 27(0.75,2.9) 28(0.25,2.9) 29(-0.25,2.9) 30(-0.75,2.9)
  rrect5% 2.2x4.6 smd paste-3: 31(0,0)
  rrect10% 0.98x0.96 on Top Paste: 31A(-0.59,1.74) 31A(-0.59,0.58) 31A(-0.59,-0.58) 31A(-0.59,-1.74) 31A(0.59,1.74) 31A(0.59,0.58) 31A(0.59,-0.58) 31A(0.59,-1.74)
  silkscreen extent -2.17,-3.18 2.17,3.18, body extent -2,-3 2,3, height 0.77
SMA [mm] "Molded Diode, 2-Leads, Body 4.3x2.6mm, IPC Medium Density, based on OnSemi component dimensions and land pattern"
  rect 2x2 smd: 1(-2,0) 2(2,0)
  silkscreen extent -3.66,-1.57 2.79,1.57, body extent -2.6,-1.3 2.6,1.3, height 2.42
SML-P1_RED [mm] "ROHM"
  rect 0.5x0.6 smd: 1(-0.45,0) 2(0.45,0)
  silkscreen extent -0.95,-0.3 -0.95,0.3, body extent -0.52,-0.33 0.52,0.33, height 0.25
SOD-123 [mm] "On Semi recommended land pattern"
  rect 0.915x1.22 smd: 1(-1.637,0) 2(1.637,0)
  silkscreen extent -2.74,-1.17 2.03,1.17, body extent -1.93,-0.9 1.93,0.9, height 1.35
SOD-128 [mm] "SMD, 2-Leads, Body 4x2.7mm, Height 1.1mm"
  rect 1.4x2.1 smd paste-0.1: 1(-2.2,0) 2(2.2,0)
  silkscreen extent -3.45,-1.45 2.95,1.45, body extent -2.5,-1.35 2.5,1.35, height 1.11
XAL4020 [mil] "Coilcraft XAL4020 7/18/12"
  rect 38x146 smd: 1(-46.5,0) 2(46.5,0)
  silkscreen extent -84,-84 84,84, body extent -84,-84 84,84, height 83
XAL5030 [mil] "Coilcraft XAL5030 12/12/11"
  rect 46x183 smd: 1(-65,0) 2(65,0)
  silkscreen extent -108,-112 108,112, body extent -108,-112 108,112, height 122
XFL3010 [mm] "Coilcraft"
  rect 1.12x3.2 smd: 1(-1.04,0) 2(1.04,0)
  body extent -1.6,-1.6 1.6,1.6, height 1.1

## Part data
C1 C2 C3 C8 Cbias1: "CAP, CERM, 0.1 µF, 16 V, +/- 10%, X7R, AEC-Q200 Grade 1, 0603", Cap_Case=0603, Manufacturer=MuRata, Supplier Part Number 1=490-8015-1-ND, TempCo=X7R, Tolerance_%=10, Value1=Unknown, Value2=16V, ValueDisplayed=0.1µF
C4: library part CMP-0008706-2, "CAP, CERM, 10 uF, 35 V, +/- 20%, X7R, 1206_190", Cap_Case=1206, Manufacturer=TDK, Supplier Part Number 1=445-8034-1-ND, TempCo=X7R, Tolerance_%=20%, Value1=Unknown, Value2=35V, ValueDisplayed=10uF
C6 C13 C29: library part CMP-0007377-4, "CAP, CERM, 0.01 uF, 16 V, +/- 10%, X7R, 0603", Cap_Case=0603, Manufacturer=MuRata, Supplier Part Number 1=490-1525-1-ND, TempCo=X7R, Tolerance_%=10%, Value1=Unknown, Value2=16V, ValueDisplayed=0.01uF
C9 C17 C18 C21: library part CMP-0007497-5, "CAP, CERM, 10 uF, 10 V, +/- 20%, X7R, 0603", Cap_Case=0603, Manufacturer=MuRata, Supplier Part Number 1=81-GRM188Z71A106MA3D, TempCo=X7R, Tolerance_%=20%, Value1=Unknown, Value2=10V, ValueDisplayed=10uF
C10: library part CMP-0007413-4, "CAP, CERM, 0.18 uF, 25 V, +/- 10%, X7R, 0603", Cap_Case=0603, Manufacturer=MuRata, Supplier Part Number 1=GRM188R71E184KA88D-ND, TempCo=X7R, Tolerance_%=10%, Value1=Unknown, Value2=25V, ValueDisplayed=0.18uF
C11 C23 C28: library part CMP-0007378-5, "CAP, CERM, 0.1 uF, 16 V, +/- 10%, X7R, 0603", Cap_Case=0603, Manufacturer=MuRata, Supplier Part Number 1=490-1532-1-ND, TempCo=X7R, Tolerance_%=10%, Value1=Unknown, Value2=16V, ValueDisplayed=0.1uF
C12: library part CMP-0007378-5, "CAP, CERM, 0.1 uF, 16 V, +/- 10%, X7R, 0603", Cap_Case=0603, Manufacturer=MuRata, PartNumber=GRM188R71C104KA01D, Supplier Part Number 1=490-1532-1-ND, TempCo=X7R, Tolerance_%=10%, Value1=Unknown, Value2=16V, ValueDisplayed=0.1uF
C15 C26: library part CMP-0007499-4, "CAP, CERM, 2.2 uF, 16 V, +/- 10%, X7R, 0603", Cap_Case=0603, Manufacturer=MuRata, Supplier Part Number 1=81-GRM188Z71C225KE3D, TempCo=X7R, Tolerance_%=10%, Value1=Unknown, Value2=16V, ValueDisplayed=2.2uF
C16: library part CMP-0007136-5, "CAP, CERM, 1 uF, 16 V, +/- 10%, X7R, AEC-Q200 Grade 1, 0603", Cap_Case=0603, Manufacturer=MuRata, Supplier Part Number 1=490-5241-6-ND, TempCo=X7R, Tolerance_%=10%, Value1=Unknown, Value2=16V, ValueDisplayed=1uF
C19: library part CMP-0006360-2, "CAP, CERM, 470 pF, 50 V, +/- 10%, X7R, AEC-Q200 Grade 1, 0402", Cap_Case=0402, Manufacturer=MuRata, Supplier Part Number 1=490-4913-1-ND, TempCo=X7R, Tolerance_%=10%, Value1=Unknown, Value2=50V, ValueDisplayed=470pF
C20: library part CMP-0006251-2, "CAP, CERM, 68 pF, 50 V, +/- 5%, C0G/NP0, 0402", Cap_Case=0402, Manufacturer=TDK, Supplier Part Number 1=445-1245-1-ND, TempCo=C0G/NP0, Tolerance_%=5%, Value1=Unknown, Value2=50V, ValueDisplayed=68pF
C22: library part CMP-0007158-5, "CAP, CERM, 22 uF, 10 V, +/- 20%, X5R, 0603", Cap_Case=0603, Manufacturer=MuRata, PartNumber=GRM187R61A226ME15D, Supplier Part Number 1=490-13243-1-ND, TempCo=X5R, Tolerance_%=20%, Value1=Unknown, Value2=10V, ValueDisplayed=22uF
C24 C25: library part CMP-0007094-5, "CAP, CERM, 0.22 uF, 50 V, +/- 10%, X7R, AEC-Q200 Grade 1, 0603", Cap_Case=0603, Manufacturer=TDK, Supplier Part Number 1=445-6926-1-ND, TempCo=X7R, Tolerance_%=10%, Value1="0.021699 ohm", Value2=50V, ValueDisplayed=0.22uF
CB: "CAP, CERM, 0.47uF, 25V, +/-10%, X5R, 0603", Cap_Case=0603, Manufacturer=MuRata, Supplier Part Number 1=GRM188R61E474KA12D-ND, TempCo=X5R, Tolerance_%=10, Value1=Unknown, Value2=25V, ValueDisplayed=0.47µF
Cbulk1: "CAP, Aluminum Polymer, 100 µF, 50 V, +/- 20%, 0.025 ohm, AEC-Q200 Grade 2, D10xL10mm SMD", Cap_Case=10x10mm, Manufacturer=Chemi-Con, Supplier Part Number 1=565-4187-1-ND, Tolerance_%=20, Value1="0.025 ohm", Value2=50V, ValueDisplayed=100µF
CF1 CF2: library part CMP-0008702-2, "CAP, CERM, 4.7 uF, 50 V, +/- 10%, X7R, 1206", Cap_Case=1206_180, Manufacturer=TDK, Supplier Part Number 1=445-8032-1-ND, TempCo=X7R, Tolerance_%=10%, Value1="0.003158 ohm", Value2=50V, ValueDisplayed=4.7uF
CFF: "CAP, CERM, 4.7 pF, 50 V, +/- 5%, C0G/NP0, 0603", Cap_Case=0603, Manufacturer=AVX, Supplier Part Number 1=478-1159-1-ND, TempCo=C0G/NP0, Tolerance_%=5, Value1="0.633 ohm", Value2=50V, ValueDisplayed=4.7pF
CI1 CO: "CAP, CERM, 0.47 µF, 50 V, +/- 10%, X7R, 0805", Cap_Case=0805, Manufacturer=MuRata, Supplier Part Number 1=490-3328-1-ND, TempCo=X7R, Tolerance_%=10, Value1=Unknown, Value2=50V, ValueDisplayed=0.47µF
CI2: "CAP, CERM, 10 µF, 50 V, +/- 10%, X7R, 1210", Cap_Case=1210, Manufacturer=MuRata, Supplier Part Number 1=490-6544-1-ND, TempCo=X7R, Tolerance_%=10, Value1=Unknown, Value2=50V, ValueDisplayed=10µF
CI3 CI4: library part CMP-0007836-2, "CAP, CERM, 2.2 uF, 50 V, +/- 10%, X5R, 0805", Cap_Case=0805, Manufacturer=TDK, Supplier Part Number 1=445-5976-1-ND, TempCo=X5R, Tolerance_%=10%, Value1="0.00366 ohm", Value2=50V, ValueDisplayed=2.2uF
CO1 CO2 CO3 CO4 CO5: "CAP, CERM, 22 µF, 16 V, +/- 10%, X7R, 1210", Cap_Case=1210, Manufacturer=MuRata, Supplier Part Number 1=490-4524-1-ND, TempCo=X7R, Tolerance_%=10, Value1="0.003 ohm", Value2=16V, ValueDisplayed=22µF
CSS: "CAP, CERM, 0.01 µF, 100 V, +/- 20%, X7R, 0603", Cap_Case=0603, Manufacturer=AVX, Supplier Part Number 1=478-3701-1-ND, TempCo=X7R, Tolerance_%=20, Value1="0.098 ohm", Value2=100V, ValueDisplayed=0.01µF
CVCC: "CAP, CERM, 2.2uF, 10V, +/-10%, X6S, 0603", Cap_Case=0603, Manufacturer=MuRata, Supplier Part Number 1=490-4521-1-ND, TempCo=X6S, Tolerance_%=10, Value1=Unknown, Value2=10V, ValueDisplayed=2.2µF
D1: library part CMP-0005456-2, "Diode, TVS, Bi, 28 V, SMA", Manufacturer=Littelfuse, Power_W=3.3W, Supplier Part Number 1=SMAJ28CALFDKR-ND
D2 D7 D8 D9 D10: library part CMP-0002872-1, "LED, Red, SMD", Color=red, Manufacturer=Rohm, Supplier Part Number 1=511-1593-1-ND, Value1=W, Value2=2V
D3 D4: library part CMP-0080760-1, "Diode, Schottky, 100 V, 0.15 A, AEC-Q101, SOD-123", Manufacturer=Vishay-Semiconductor, Supplier Part Number 1=BAT46W-E3-08CT-ND, Value1=0.15A, Value2=1V
D5: library part CMP-0005768-2, "Diode, Zener, 15 V, 370 mW, AEC-Q101, SOD-123", Manufacturer="Diodes Inc.", Power_W=370mW, Supplier Part Number 1=BZT52C15-FDICT-ND, Value1=0.37W
D6: library part CMP-0028872-2, "Diode, Schottky, 30 V, 2 A, SOD-128", Manufacturer=Panasonic, Supplier Part Number 1=DB2430100LCT-ND, Value1=2A, Value2=0.39V
FB1: "Ferrite Bead, 800 ohm @ 100 MHz, 8 A, 2220", Manufacturer="Laird-Signal Integrity Products", Supplier Part Number 1=240-2433-1-ND, Value1="0.01 ohm", Value2=8A, ValueDisplayed="800 ohm"
FID1 FID2 FID3: "Fiducial mark.  There is nothing to buy or mount.", Manufacturer=N/A
H1 H2 H3 H4: "Machine Screw, Round, #4-40 x 1/4, Nylon, Philips panhead", DigiKeyPartNumber=H542-ND, Manufacturer="B&F Fastener Supply"
H5 H6 H7 H8: "Standoff, Hex, 0.5\"L #4-40 Nylon", Manufacturer=Keystone, Supplier Part Number 1=36-1902C-ND
J1: library part CMP-0002338-1, "Header, 100mil, 3x1, Tin, TH", Color=Black, Current_A=3A, Manufacturer="Sullins Connector Solutions", Supplier Part Number 1=S1012E-03-ND, Voltage_V=1.8kV
L1: "Inductor, Shielded, Composite, 2.2 µH, 9.2 A, 0.01 ohm, SMD", Manufacturer=Coilcraft, Value1="0.01 ohm", Value2=9.2A, ValueDisplayed=2.2µH
L2: library part CMP-0061128-1, "Inductor, Shielded, Composite, 1 uH, 2.3 A, 0.04 ohm, SMD", Manufacturer=Coilcraft, Value1="0.04 ohm", Value2=2.3A, ValueDisplayed=1uH
L3: library part CMP-0058761-1, "Inductor, Multilayer, Ferrite, 2.2 uH, 1.2 A, 0.11 ohm, SMD", Manufacturer=MuRata, Supplier Part Number 1=490-7786-1-ND, Value1="0.11 ohm", Value2=1.2A, ValueDisplayed=2.2uH
LF1: library part CMP-0060988-1, "Inductor, Shielded, Composite, 600 nH, 10.38 A, 0.01 ohm, SMD", Manufacturer=Coilcraft, Value1="0.01 ohm", Value2=10.38A, ValueDisplayed=600nH
Logo2: library part Pb-Free
Logo3: library part FCC_disclaimer, "FCC_disclaimer"
NTGND1 NTGND2: "Single point connection between nets."
P1 P3: library part 6091, "Standard Banana Jack, Insulated, Red", Manufacturer=Keystone, Supplier Part Number 1=6091K-ND
P2 P4: library part 6092, "Standard Banana Jack, Insulated, Black", Manufacturer=Keystone, Supplier Part Number 1=6092K-ND
Q1: library part CMP-0000140-2, "MOSFET, P-CH, -60 V, -30 A, PowerPAK_SO-8L", Alternate Manufacturer=None, Manufacturer=Vishay-Siliconix, PartNumber=SQJ461EP, Supplier Part Number 1=SQJ461EP-T1-GE3-ND, Value1=0.03, Value2="90 nC"
R1: library part CMP-0026994-4, "RES, 10 k, 5%, 0.1 W, AEC-Q200 Grade 0, 0402", Manufacturer=Panasonic, Power_W=100mW, Supplier Part Number 1=P10KJCT-ND, TempCo="200 ppm/C", Tolerance_%=5%, Value2=0.1W, Value_Code=10k0, ValueDisplayed=10k
R2: library part CMP-0026936-3, "RES, 47, 5%, 0.063 W, AEC-Q200 Grade 0, 0402", Manufacturer=Vishay-Dale, Power_W=63mW, Supplier Part Number 1=541-47JCT-ND, TempCo="200 ppm/C", Tolerance_%=5%, Value2=0.063W, Value_Code=47R0, ValueDisplayed=47
R3: library part CMP-0018374-2, "RES, 560, 1%, 0.25 W, 1206", Manufacturer="Yageo America", Power_W=250mW, Supplier Part Number 1=311-560FRCT-ND, TempCo="100 ppm/C", Tolerance_%=1%, Value2=0.25W, Value_Code=560R, ValueDisplayed=560
R4: library part CMP-0025931-5, "RES, 56 k, 5%, 0.1 W, 0603", Manufacturer=Yageo, Power_W=100mW, Supplier Part Number 1=311-56KGRCT-ND, TempCo="100 ppm/C", Tolerance_%=5%, Value2=0.1W, Value_Code=56k0, ValueDisplayed=56k
R5 R6 R8 R9 R10 R12 RFBT: library part CMP-0021990-4, "RES, 100 k, 1%, 0.1 W, AEC-Q200 Grade 0, 0603", Manufacturer=Vishay-Dale, Power_W=100mW, Supplier Part Number 1=541-100KHCT-ND, TempCo="100 ppm/C", Tolerance_%=1%, Value2=0.1W, Value_Code=100k
R7: library part CMP-0021998-4, "RES, 10.0 k, 1%, 0.1 W, AEC-Q200 Grade 0, 0603", Manufacturer=Vishay-Dale, PartNumber=CRCW060310K0FKEA, Power_W=100mW, Supplier Part Number 1=541-10.0KHCT-ND, TempCo="100 ppm/C", Tolerance_%=1%, Value2=0.1W, Value_Code=10k0, ValueDisplayed=10.0k
R7: library part CMP-0021998-4, "RES, 10.0 k, 1%, 0.1 W, AEC-Q200 Grade 0, 0603", Manufacturer=Vishay-Dale, Power_W=100mW, Supplier Part Number 1=541-10.0KHCT-ND, TempCo="100 ppm/C", Tolerance_%=1%, Value2=0.1W, Value_Code=10k0, ValueDisplayed=10.0k
R11: "RES, 0, 5%, 0.1 W, 0603", Manufacturer=Vishay-Dale, Power_W=0.1, Supplier Part Number 1=541-0.0GCT-ND, TempCo="200 ppm/C", Tolerance_%=5, Value1=5%, Value2=0.1W, Value_Code=0000, ValueDisplayed=0
R13: library part CRCW06030000Z0EA, "RES, 0, 5%, 0.1 W, 0603", Manufacturer=Vishay-Dale, Power_W=0.1, Supplier Part Number 1=541-0.0GCT-ND, TempCo="200 ppm/C", Tolerance_%=5, Value1=5%, Value2=0.1W, Value_Code=0000, ValueDisplayed=0
R14: library part CMP-0026231-2, "RES, 2.20 k, 1%, 0.063 W, AEC-Q200 Grade 0, 0402", Manufacturer=Vishay-Dale, Power_W=63mW, Supplier Part Number 1=541-2.20KLCT-ND, TempCo="100 ppm/C", Tolerance_%=1%, Value2=0.063W, Value_Code=2k20, ValueDisplayed=2.20k
R15 R16 R17 R18: library part CMP-0026071-3, "RES, 1.00 k, 1%, 0.063 W, AEC-Q200 Grade 0, 0402", Manufacturer=Vishay-Dale, Power_W=63mW, Supplier Part Number 1=541-1.00KLCT-ND, TempCo="100 ppm/C", Tolerance_%=1%, Value2=0.063W, Value_Code=1k00, ValueDisplayed=1.00k
R19: library part CMP-0022618-3, "RES, 825 k, 1%, 0.1 W, AEC-Q200 Grade 0, 0603", Manufacturer=Vishay-Dale, Power_W=100mW, Supplier Part Number 1=541-825KHCT-ND, TempCo="100 ppm/C", Tolerance_%=1%, Value2=0.1W, Value_Code=825k
R20: library part CMP-0022497-4, "RES, 562 k, 1%, 0.1 W, AEC-Q200 Grade 0, 0603", Manufacturer=Vishay-Dale, Power_W=100mW, Supplier Part Number 1=541-562KHCT-ND, TempCo="100 ppm/C", Tolerance_%=1%, Value2=0.1W, Value_Code=562k
Rbias1: "RES, 3.0, 5%, 0.063 W, 0402", Manufacturer=Vishay-Dale, Power_W=0.063, Supplier Part Number 1=541-3.0JCT-ND, TempCo="200 ppm/C", Tolerance_%=5, Value1=5%, Value2=0.063W, Value_Code=3R00, ValueDisplayed=3.0
RFBB: library part CMP-0022422-4, "RES, 43.2 k, 1%, 0.1 W, AEC-Q200 Grade 0, 0603", Manufacturer=Vishay-Dale, Power_W=100mW, Supplier Part Number 1=541-43.2KHCT-ND, TempCo="100 ppm/C", Tolerance_%=1%, Value2=0.1W, Value_Code=43k2, ValueDisplayed=43.2k
RPG: "RES, 100 k, 1%, 0.1 W, 0603", Manufacturer=Vishay-Dale, Power_W=0.1, Supplier Part Number 1=541-100KHCT-ND, TempCo="100 ppm/C", Tolerance_%=1, Value1=1%, Value2=0.1W, Value_Code=100k
RT: "RES, 17.4 k, 1%, 0.1 W, 0603", Manufacturer=Vishay-Dale, Power_W=0.1, Supplier Part Number 1=541-17.4KHCT-ND, TempCo="100 ppm/C", Tolerance_%=1, Value1=1%, Value2=0.1W, Value_Code=17k4, ValueDisplayed=17.4k
TP1: library part CMP-0055156-1, "Test Point, Multipurpose, Blue, TH", Color=Blue, Manufacturer=Keystone, PartNumber=5127, Supplier Part Number 1=36-5127-ND
TP2 TP9 TP11 TP15 TP18: library part CMP-0055147-1, "Test Point, Multipurpose, Red, TH", Color=Red, Manufacturer=Keystone, PartNumber=5010, Supplier Part Number 1=36-5010-ND
TP3 TP14: library part CMP-0055158-1, "Test Point, Multipurpose, Green, TH", Color=Green, Manufacturer=Keystone, PartNumber=5126, Supplier Part Number 1=36-5126-ND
